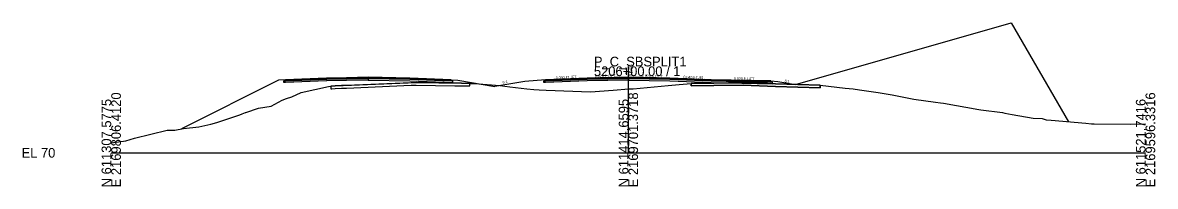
# Model space of a CAD drawing. Extents: x -26 to 1303, y -3010 to 12033.
# Drawn here: x 974.3 to 1302.8, y 4990.3 to 5037.7 of the extents above; entities that cross this region are included whole.
import ezdxf

# ---------------------------------------------------------------- set-up
doc = ezdxf.new("R2010")
doc.units = 0
for name, color, linetype in [('RD_GPK_XS_Cell', 7, 'Continuous'), ('RD_Sketch10', 7, 'Continuous'), ('RD_XS_Base', 7, 'Continuous'), ('RD_XS_ExGround', 7, 'Continuous'), ('RD_XS_ExPaveRet', 7, 'Continuous'), ('RD_XS_Greenside', 7, 'Continuous'), ('RD_XS_Pave', 7, 'Continuous'), ('RD_XS_PaveOvlay_CP', 7, 'Continuous'), ('RD_XS_TieSlope', 7, 'Continuous'), ('RD_XS_TX_Elev_EX', 7, 'Continuous'), ('RD_XS_TX_Elev_PR', 7, 'Continuous'), ('RD_XS_TX_Slope', 7, 'Continuous')]:
    doc.layers.add(name, color=color, linetype=linetype)

msp = doc.modelspace()

# ---------------------------------------------------------------- linework, layer by layer
at = {"layer": 'RD_GPK_XS_Cell'}
for p, q in [((1150, 5000), (1150, 5025)), ((1000, 5000), (1150, 5000)), ((1150, 5000), (1300, 5000))]:
    msp.add_line(p, q, dxfattribs=at)
at = {"layer": 'RD_Sketch10'}
msp.add_lwpolyline([(1198.43, 5019.78), (1261, 5037.65), (1277.64, 5008.98)], dxfattribs=at)
at = {"layer": 'RD_XS_Base'}
for p, q in [((1050.05, 5020.8), (1050.55, 5020.82)), ((1050.05, 5020.79), (1050.05, 5020.8)), ((1050.05, 5020.3), (1050.05, 5020.79)), ((1050.55, 5020.32), (1050.05, 5020.3)), ((1050.55, 5020.82), (1062.48, 5021.3)), ((1050.55, 5020.82), (1050.55, 5020.82)), ((1062.48, 5020.8), (1050.55, 5020.32)), ((1050.55, 5020.32), (1050.55, 5020.32)), ((1062.48, 5021.3), (1062.56, 5021.3)), ((1062.56, 5020.8), (1062.48, 5020.8)), ((1062.56, 5021.3), (1068.26, 5021.42)), ((1068.26, 5020.92), (1062.56, 5020.8)), ((1068.26, 5021.42), (1074.56, 5021.54)), ((1074.56, 5021.04), (1068.26, 5020.92)), ((1074.56, 5021.54), (1074.56, 5021.7)), ((1074.56, 5021.7), (1074.56, 5021.05)), ((1074.56, 5021.54), (1074.56, 5021.7)), ((1074.56, 5021.7), (1074.56, 5021.04)), ((1074.56, 5021.54), (1074.56, 5021.05)), ((1074.56, 5021.54), (1074.56, 5021.54)), ((1074.56, 5021.54), (1074.56, 5021.04)), ((1086.56, 5021.3), (1074.56, 5021.54)), ((1074.56, 5021.54), (1074.56, 5021.54)), ((1074.56, 5021.05), (1074.56, 5021.04)), ((1074.56, 5021.05), (1074.56, 5021.04)), ((1074.56, 5021.04), (1074.56, 5021.04)), ((1074.56, 5021.04), (1074.56, 5021.04)), ((1074.56, 5021.04), (1086.56, 5020.8)), ((1098.56, 5020.82), (1086.56, 5021.3)), ((1086.56, 5020.8), (1099.06, 5020.3)), ((1088.56, 5021.22), (1088.56, 5021.22)), ((1088.56, 5020.72), (1088.56, 5020.72)), ((1099.06, 5020.8), (1098.56, 5020.82)), ((1098.56, 5020.82), (1098.56, 5020.82)), ((1099.06, 5020.3), (1099.06, 5020.8)), ((1099.06, 5020.8), (1099.06, 5020.8)), ((1099.06, 5020.3), (1099.06, 5020.3)), ((1099.06, 5020.3), (1099.06, 5020.3)), ((1125.5, 5020.8), (1126, 5020.82)), ((1125.5, 5020.3), (1125.5, 5020.8)), ((1125.5, 5020.8), (1125.5, 5020.8)), ((1126, 5020.32), (1125.5, 5020.3)), ((1125.5, 5020.3), (1125.5, 5020.3)), ((1125.5, 5020.3), (1125.5, 5020.3)), ((1126, 5020.82), (1138, 5021.3)), ((1126, 5020.82), (1126, 5020.82)), ((1138, 5020.8), (1126, 5020.32)), ((1126, 5020.32), (1126, 5020.32)), ((1136, 5021.22), (1136, 5021.22)), ((1136, 5020.72), (1136, 5020.72)), ((1138, 5021.3), (1150, 5021.54)), ((1150, 5021.04), (1138, 5020.8)), ((1150, 5021.54), (1150, 5021.7)), ((1150, 5021.7), (1150, 5021.04)), ((1150, 5021.54), (1150, 5021.04)), ((1150, 5021.54), (1150, 5021.54)), ((1162, 5021.3), (1150, 5021.54)), ((1150, 5021.54), (1150, 5021.54)), ((1150, 5021.04), (1150, 5021.04)), ((1150, 5021.04), (1150, 5021.04)), ((1150, 5021.04), (1162, 5020.8)), ((1174, 5020.82), (1162, 5021.3)), ((1162, 5021.3), (1162, 5021.3)), ((1162, 5020.8), (1162, 5020.8)), ((1162, 5020.8), (1174, 5020.32)), ((1191.3, 5020.48), (1174, 5020.82)), ((1174, 5020.82), (1174, 5020.82)), ((1174, 5020.32), (1174, 5020.32)), ((1174, 5020.32), (1191.8, 5019.97)), ((1191.8, 5020.47), (1191.3, 5020.48)), ((1191.3, 5020.48), (1191.3, 5020.48)), ((1191.8, 5019.97), (1191.8, 5020.47)), ((1191.8, 5020.47), (1191.8, 5020.47)), ((1191.8, 5019.97), (1191.8, 5019.97)), ((1191.8, 5019.97), (1191.8, 5019.97))]:
    msp.add_line(p, q, dxfattribs=at)
at = {"layer": 'RD_XS_ExGround'}
msp.add_lwpolyline([(1000, 5002.93), (1004.2, 5003.47), (1006.71, 5004.23), (1016.21, 5006.57), (1018.43, 5006.57), (1021, 5007.03), (1025.43, 5007.49), (1028.84, 5008.29), (1030.6, 5008.75), (1037.26, 5011.02), (1038.01, 5011.27), (1038.98, 5011.65), (1039.02, 5011.66), (1042.67, 5012.91), (1046.37, 5013.5), (1049.62, 5015.22), (1050.81, 5015.72), (1052.37, 5016.24), (1055.12, 5017.5), (1063.03, 5019.15), (1063.73, 5019.3), (1064.97, 5019.36), (1088.48, 5020.34), (1101.58, 5020.14), (1104.04, 5020.1), (1105.35, 5020.01), (1112.69, 5019.5), (1115.59, 5019.14), (1120.58, 5018.49), (1122.54, 5018.32), (1124.12, 5018.26), (1126.14, 5018.13), (1138.98, 5017.63), (1145.59, 5018.11), (1150.1, 5018.5), (1151.43, 5018.5), (1161.53, 5019.43), (1164.68, 5019.73), (1168.24, 5020.09), (1174.74, 5020.18), (1183.3, 5020.3), (1192.69, 5019.98), (1205.64, 5019.53), (1212.91, 5018.73), (1215.2, 5018.5), (1217.07, 5018.2), (1222.4, 5017.48), (1226.48, 5016.73), (1229.9, 5016.09), (1232.8, 5015.53), (1239.11, 5014.68), (1240.53, 5014.5), (1241.42, 5014.34), (1251.61, 5012.55), (1252.27, 5012.44), (1258.49, 5011.62), (1259.2, 5011.5), (1261.35, 5011.1), (1267.43, 5010.04), (1270.05, 5009.94), (1271.18, 5009.52), (1272.66, 5009.43), (1282.63, 5008.53), (1284.32, 5008.38), (1285.12, 5008.38), (1295.57, 5008.29), (1300, 5008.35)], dxfattribs=at)
at = {"layer": 'RD_XS_ExPaveRet'}
for points in [[(1066.82, 5019.43), (1064.97, 5019.36), (1063.97, 5019.31), (1063.73, 5019.3), (1063.73, 5019.12), (1063.73, 5018.55), (1063.97, 5018.56), (1064.97, 5018.61), (1066.82, 5018.68), (1068.26, 5018.74), (1087.02, 5019.53), (1088.48, 5019.59), (1099.64, 5019.42), (1101.58, 5019.39), (1104.04, 5019.35), (1104.04, 5019.35), (1104.04, 5019.35), (1104.04, 5019.35), (1104.04, 5020), (1104.04, 5020.1), (1104.04, 5020.1), (1104.04, 5020.1), (1104.04, 5020.1), (1101.58, 5020.14), (1099.64, 5020.17), (1088.48, 5020.34), (1087.02, 5020.28), (1068.26, 5019.49), (1066.82, 5019.43)], [(1066.82, 5019.43), (1064.97, 5019.36), (1063.97, 5019.31), (1063.73, 5019.3), (1063.73, 5019.12), (1063.73, 5018.55), (1063.97, 5018.56), (1064.97, 5018.61), (1066.82, 5018.68), (1068.26, 5018.74), (1087.02, 5019.53), (1088.48, 5019.59), (1099.64, 5019.42), (1101.58, 5019.39), (1104.04, 5019.35), (1104.04, 5019.35), (1104.04, 5020), (1104.04, 5020.1), (1104.04, 5020.1), (1101.58, 5020.14), (1099.64, 5020.17), (1088.48, 5020.34), (1087.02, 5020.28), (1068.26, 5019.49), (1066.82, 5019.43)], [(1205.64, 5019.53), (1205.64, 5019.53), (1205.64, 5018.78), (1205.64, 5018.78), (1205.64, 5018.78), (1192.69, 5019.23), (1192.69, 5019.23), (1183.3, 5019.55), (1183.3, 5019.55), (1174.74, 5019.43), (1174.74, 5019.43), (1168.24, 5019.34), (1168.24, 5020.09), (1168.24, 5020.09), (1174.74, 5020.18), (1174.74, 5020.18), (1183.3, 5020.3), (1183.3, 5020.3), (1192.69, 5019.98), (1192.69, 5019.98), (1205.64, 5019.53), (1205.64, 5019.53), (1205.64, 5019.53)], [(1205.64, 5019.53), (1192.69, 5019.98), (1183.3, 5020.3), (1174.74, 5020.18), (1168.24, 5020.09), (1168.24, 5019.34), (1174.74, 5019.43), (1183.3, 5019.55), (1192.69, 5019.23), (1205.64, 5018.78), (1205.64, 5018.78), (1205.64, 5019.53), (1205.64, 5019.53)]]:
    msp.add_lwpolyline(points, dxfattribs=at)
at = {"layer": 'RD_XS_Greenside'}
for p, q in [((1048.55, 5020.98), (1020.4, 5006.91)), ((1100.56, 5020.98), (1111.24, 5019.2)), ((1120, 5020.66), (1111.24, 5019.2)), ((1193.3, 5020.63), (1198.43, 5019.78))]:
    msp.add_line(p, q, dxfattribs=at)
at = {"layer": 'RD_XS_Pave'}
for p, q in [((1062.48, 5021.62), (1050.55, 5021.14)), ((1062.48, 5021.46), (1050.55, 5020.98)), ((1050.55, 5020.98), (1062.48, 5021.46)), ((1050.55, 5020.82), (1062.48, 5021.3)), ((1050.55, 5021.14), (1050.55, 5021.14)), ((1050.55, 5021.14), (1050.55, 5020.98)), ((1050.55, 5020.98), (1050.55, 5020.98)), ((1050.55, 5020.98), (1050.55, 5020.82)), ((1062.56, 5021.62), (1062.48, 5021.62)), ((1062.56, 5021.46), (1062.48, 5021.46)), ((1062.48, 5021.46), (1062.56, 5021.46)), ((1062.48, 5021.3), (1062.56, 5021.3)), ((1068.26, 5021.73), (1062.56, 5021.62)), ((1068.26, 5021.58), (1062.56, 5021.46)), ((1062.56, 5021.46), (1068.26, 5021.58)), ((1062.56, 5021.3), (1068.26, 5021.42)), ((1074.56, 5021.86), (1068.26, 5021.73)), ((1074.56, 5021.7), (1068.26, 5021.58)), ((1068.26, 5021.58), (1074.56, 5021.7)), ((1068.26, 5021.42), (1074.56, 5021.54)), ((1086.56, 5021.62), (1074.56, 5021.86)), ((1074.56, 5021.54), (1074.56, 5021.7)), ((1074.56, 5021.7), (1074.56, 5021.54)), ((1074.56, 5021.54), (1074.56, 5021.7)), ((1074.56, 5021.7), (1086.56, 5021.46)), ((1086.56, 5021.46), (1074.56, 5021.7)), ((1074.56, 5021.7), (1074.56, 5021.54)), ((1074.56, 5021.54), (1074.56, 5021.54)), ((1074.56, 5021.54), (1074.56, 5021.54)), ((1074.56, 5021.54), (1074.56, 5021.54)), ((1074.56, 5021.54), (1074.56, 5021.54)), ((1074.56, 5021.54), (1086.56, 5021.3)), ((1098.56, 5021.14), (1086.56, 5021.62)), ((1086.56, 5021.46), (1098.56, 5020.98)), ((1098.56, 5020.98), (1086.56, 5021.46)), ((1086.56, 5021.3), (1098.56, 5020.82)), ((1088.56, 5021.54), (1088.56, 5021.54)), ((1088.56, 5021.38), (1088.56, 5021.38)), ((1088.56, 5021.38), (1088.56, 5021.38)), ((1088.56, 5021.22), (1088.56, 5021.22)), ((1098.56, 5020.98), (1098.56, 5021.14)), ((1098.56, 5021.14), (1098.56, 5021.14)), ((1098.56, 5020.98), (1098.56, 5020.98)), ((1098.56, 5020.98), (1098.56, 5020.98)), ((1098.56, 5020.82), (1098.56, 5020.98)), ((1098.56, 5020.98), (1098.56, 5020.98)), ((1098.56, 5020.82), (1098.56, 5020.82)), ((1098.56, 5020.82), (1098.56, 5020.82)), ((1138, 5021.62), (1126, 5021.14)), ((1138, 5021.46), (1126, 5020.98)), ((1126, 5020.98), (1138, 5021.46)), ((1126, 5020.82), (1138, 5021.3)), ((1126, 5021.14), (1126, 5021.14)), ((1126, 5021.14), (1126, 5020.98)), ((1126, 5020.98), (1126, 5020.98)), ((1126, 5020.98), (1126, 5020.82)), ((1126, 5020.98), (1126, 5020.98)), ((1126, 5020.98), (1126, 5020.98)), ((1126, 5020.82), (1126, 5020.82)), ((1126, 5020.82), (1126, 5020.82)), ((1136, 5021.54), (1136, 5021.54)), ((1136, 5021.38), (1136, 5021.38)), ((1136, 5021.38), (1136, 5021.38)), ((1136, 5021.22), (1136, 5021.22)), ((1150, 5021.86), (1138, 5021.62)), ((1150, 5021.7), (1138, 5021.46)), ((1138, 5021.46), (1150, 5021.7)), ((1138, 5021.3), (1150, 5021.54)), ((1162, 5021.62), (1150, 5021.86)), ((1150, 5021.54), (1150, 5021.7)), ((1150, 5021.7), (1162, 5021.46)), ((1162, 5021.46), (1150, 5021.7)), ((1150, 5021.7), (1150, 5021.7)), ((1150, 5021.7), (1150, 5021.54)), ((1150, 5021.54), (1150, 5021.54)), ((1150, 5021.54), (1150, 5021.54)), ((1150, 5021.54), (1150, 5021.54)), ((1150, 5021.54), (1162, 5021.3)), ((1174, 5021.14), (1162, 5021.62)), ((1162, 5021.62), (1162, 5021.62)), ((1162, 5021.46), (1162, 5021.46)), ((1162, 5021.46), (1174, 5020.98)), ((1174, 5020.98), (1162, 5021.46)), ((1162, 5021.46), (1162, 5021.46)), ((1162, 5021.3), (1162, 5021.3)), ((1162, 5021.3), (1174, 5020.82)), ((1191.3, 5020.79), (1174, 5021.14)), ((1174, 5021.14), (1174, 5021.14)), ((1174, 5020.98), (1174, 5020.98)), ((1174, 5020.98), (1191.3, 5020.64)), ((1191.3, 5020.64), (1174, 5020.98)), ((1174, 5020.98), (1174, 5020.98)), ((1174, 5020.82), (1174, 5020.82)), ((1174, 5020.82), (1191.3, 5020.48)), ((1191.3, 5020.64), (1191.3, 5020.79)), ((1191.3, 5020.79), (1191.3, 5020.79)), ((1191.3, 5020.64), (1191.3, 5020.64)), ((1191.3, 5020.64), (1191.3, 5020.64)), ((1191.3, 5020.48), (1191.3, 5020.64)), ((1191.3, 5020.64), (1191.3, 5020.64)), ((1191.3, 5020.48), (1191.3, 5020.48)), ((1191.3, 5020.48), (1191.3, 5020.48))]:
    msp.add_line(p, q, dxfattribs=at)
at = {"layer": 'RD_XS_PaveOvlay_CP'}
for p, q in [((1050.55, 5021.14), (1062.56, 5021.62)), ((1062.56, 5021.62), (1068.26, 5021.73)), ((1068.26, 5021.73), (1074.56, 5021.86)), ((1074.56, 5021.86), (1086.56, 5021.62)), ((1086.56, 5021.62), (1098.56, 5021.14)), ((1138, 5021.62), (1126, 5021.14)), ((1126, 5021.14), (1126, 5021.14)), ((1136, 5021.54), (1136, 5021.54)), ((1150, 5021.86), (1138, 5021.62)), ((1162, 5021.62), (1150, 5021.86)), ((1174, 5021.14), (1162, 5021.62)), ((1162, 5021.62), (1162, 5021.62)), ((1191.3, 5020.79), (1174, 5021.14)), ((1174, 5021.14), (1174, 5021.14)), ((1191.3, 5020.79), (1191.3, 5020.79))]:
    msp.add_line(p, q, dxfattribs=at)
at = {"layer": 'RD_XS_TieSlope'}
for p, q in [((1050.55, 5021.14), (1048.55, 5020.98)), ((1098.56, 5021.14), (1100.56, 5020.98)), ((1126, 5021.14), (1120, 5020.66)), ((1191.3, 5020.79), (1193.3, 5020.63))]:
    msp.add_line(p, q, dxfattribs=at)

# ---------------------------------------------------------------- texts
at = {"layer": 'RD_GPK_XS_Cell'}
for s, p in [('P_C_SBSPLIT1', (1140, 5025)), ('5206+00.00 / 1', (1140, 5022.2)), ('EL 70', (974, 4998.6))]:
    msp.add_text(s, height=2.8, dxfattribs=at).set_placement(p)
for s, p in [('E 2169806.4120', (1002.8, 4990)), ('E 2169701.3718', (1152.8, 4990)), ('E 2169596.3316', (1302.8, 4990)), ('N 611307.5775', (1000, 4990)), ('N 611414.6595', (1150, 4990)), ('N 611521.7416', (1300, 4990))]:
    msp.add_text(s, height=2.8, rotation=90, dxfattribs=at).set_placement(p)
at = {"layer": 'RD_XS_TX_Elev_EX'}
msp.add_text('88.48', height=0.6, rotation=90, dxfattribs=at).set_placement((1149.63, 5022.7))
at = {"layer": 'RD_XS_TX_Elev_PR'}
msp.add_text('91.86', height=1, rotation=90, dxfattribs=at).set_placement((1151.23, 5022.12))
at = {"layer": 'RD_XS_TX_Slope'}
for s, rotation, p in [('6:1', 9.4642, (1113.57, 5020)), ('0.040 FT./FT.', 2.2906, (1128.93, 5021.36)), ('0.020 FT./FT.', 1.1458, (1140.27, 5021.83)), ('0.020 FT./FT.', 358.8542, (1153.94, 5021.88)), ('0.040 FT./FT.', 357.7094, (1165.94, 5021.56)), ('0.020 FT./FT.', 358.8542, (1180.59, 5021.11)), ('6:1', 350.5377, (1195.26, 5020.46))]:
    msp.add_text(s, height=0.75, rotation=rotation, dxfattribs=at).set_placement(p)

doc.saveas('drawing.dxf')
